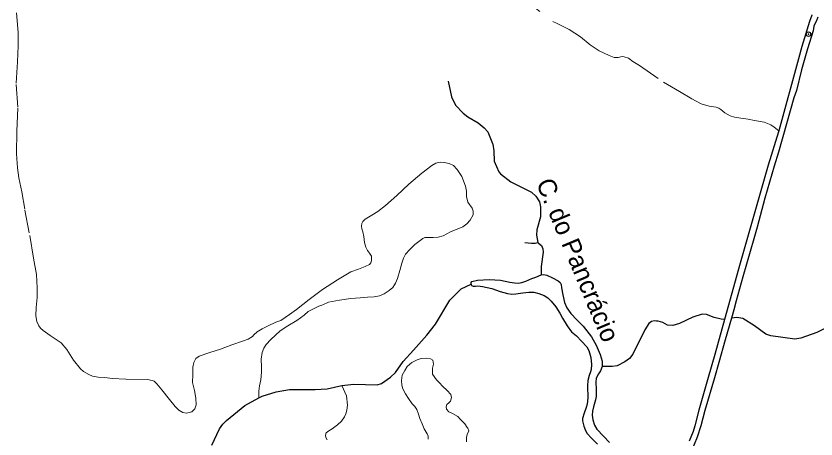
# Model space of a CAD drawing. Extents: x 267.7 to 296, y 7537.7 to 7565.8.
# Drawn here: x 282.492 to 285.983, y 7561.246 to 7563.092 of the extents above; entities that cross this region are included whole.
import ezdxf
from ezdxf.enums import TextEntityAlignment as Align

# ---------------------------------------------------------------- set-up
doc = ezdxf.new("R2010")
doc.units = 0
doc.header["$LTSCALE"] = 0.04
doc.header["$PDMODE"] = 32
doc.header["$PDSIZE"] = 0.02
doc.linetypes.add('SHORT_DASHED', pattern=[2.7, 1.5, -1.2])
for name, color, linetype, lineweight in [('1', 7, 'Continuous', 25), ('2', 7, 'Continuous', 25), ('21', 7, 'SHORT_DASHED', 13), ('7', 7, 'Continuous', 25)]:
    doc.layers.add(name, color=color, linetype=linetype, lineweight=lineweight)
doc.layers.add('61', color=7, linetype='Continuous')

msp = doc.modelspace()

# ---------------------------------------------------------------- linework, layer by layer
at = {"layer": '1'}
for points in [[(285.9657, 7563.0964), (285.9653, 7563.0956), (285.9549, 7563.0678), (285.921, 7562.9592), (285.9071, 7562.9053), (285.8206, 7562.591)], [(285.9911, 7563.087), (285.9863, 7563.0752), (285.985, 7563.072), (285.9745, 7563.0467), (285.9707, 7563.0269), (285.9464, 7562.9487), (285.9206, 7562.8574), (285.898, 7562.7671), (285.8859, 7562.7346), (285.8551, 7562.6218), (285.8204, 7562.4974), (285.8011, 7562.4363), (285.7604, 7562.297), (285.7263, 7562.1699), (285.7119, 7562.1192), (285.6641, 7561.9535), (285.6349, 7561.8489), (285.625, 7561.8093), (285.6145, 7561.7727)], [(285.8206, 7562.591), (285.8193, 7562.5864), (285.7741, 7562.4413), (285.6525, 7562.0129), (285.5847, 7561.7678)], [(285.6145, 7561.7727), (285.587, 7561.6783), (285.5595, 7561.5803), (285.5397, 7561.5137), (285.4984, 7561.37), (285.4808, 7561.3034), (285.4653, 7561.2545), (285.4521, 7561.222), (285.4477, 7561.2121), (285.3927, 7561.0866), (285.3503, 7560.9825), (285.3156, 7560.9005), (285.2639, 7560.7745), (285.2314, 7560.7012), (285.1995, 7560.6192), (285.1598, 7560.5246), (285.1424, 7560.4856)], [(285.5847, 7561.7678), (285.5421, 7561.6149), (285.5126, 7561.515), (285.4726, 7561.3724), (285.4544, 7561.3029), (285.4474, 7561.2795), (285.4292, 7561.236)]]:
    msp.add_lwpolyline(points, dxfattribs=at)
msp.add_point((285.9505, 7563.0123), dxfattribs=at)
at = {"layer": '2'}
for points in [[(284.4779, 7561.9218), (284.4782, 7561.929), (284.4813, 7561.9328), (284.5063, 7561.9389), (284.5571, 7561.9419), (284.6072, 7561.9389), (284.6474, 7561.9306), (284.6671, 7561.9268), (284.6846, 7561.926), (284.6997, 7561.9283), (284.7164, 7561.9351), (284.743, 7561.9465), (284.7612, 7561.9526), (284.7834, 7561.9622)], [(284.7834, 7561.9622), (284.7938, 7561.9639), (284.8082, 7561.9617), (284.834, 7561.9495), (284.8575, 7561.9359), (284.8666, 7561.9283), (284.8712, 7561.9207), (284.8734, 7561.9055), (284.8787, 7561.8752), (284.8856, 7561.841), (284.8954, 7561.8191), (284.9136, 7561.794), (284.9394, 7561.766), (284.9667, 7561.7386), (285.0031, 7561.6916), (285.0236, 7561.6552), (285.0418, 7561.615), (285.0502, 7561.5854), (285.0504, 7561.5627)], [(284.4779, 7561.9218), (284.4805, 7561.9161), (284.4866, 7561.9131), (284.4979, 7561.9131), (284.5078, 7561.9146), (284.5283, 7561.9108), (284.5693, 7561.9025), (284.6049, 7561.8896), (284.6375, 7561.8813), (284.6565, 7561.8782), (284.6732, 7561.8797), (284.7043, 7561.8835), (284.7301, 7561.8873), (284.7513, 7561.8866), (284.7741, 7561.8813), (284.7968, 7561.8721), (284.8135, 7561.8615), (284.8279, 7561.8471), (284.8484, 7561.8221), (284.8658, 7561.7948), (284.8765, 7561.7728), (284.8977, 7561.7402), (284.9167, 7561.7136), (284.9379, 7561.6969), (284.9607, 7561.6726), (284.9834, 7561.6476), (284.9918, 7561.6317), (285.0001, 7561.6013), (285.0031, 7561.5718), (285.0024, 7561.5498), (284.9994, 7561.5391), (284.9933, 7561.5225), (284.9872, 7561.5012), (284.9857, 7561.4785), (284.9872, 7561.4261), (284.9849, 7561.3988), (284.9804, 7561.3829), (284.9713, 7561.3586), (284.9645, 7561.3358), (284.9645, 7561.3252), (284.9698, 7561.3017), (284.9781, 7561.2827), (284.9842, 7561.2706), (285.0039, 7561.2494), (285.0305, 7561.2243)], [(285.0504, 7561.5627), (285.0426, 7561.5437), (285.0342, 7561.5308), (285.0274, 7561.5171), (285.0244, 7561.5096), (285.0229, 7561.4951), (285.0236, 7561.461), (285.0236, 7561.4314), (285.0214, 7561.417), (285.013, 7561.3859), (285.0085, 7561.3677), (285.0069, 7561.3495), (285.0092, 7561.3305), (285.016, 7561.307), (285.0267, 7561.2888), (285.0555, 7561.2592), (285.0828, 7561.2312)]]:
    msp.add_lwpolyline(points, dxfattribs=at)
at = {"layer": '21'}
for points in [[(284.6998, 7563.1725), (284.835, 7563.0678), (284.8541, 7563.0587), (284.9068, 7563.0327), (284.9557, 7563.0006), (284.9985, 7562.9662), (285.0375, 7562.9395), (285.0802, 7562.9196), (285.1031, 7562.9112), (285.1207, 7562.9105), (285.1375, 7562.9143), (285.1459, 7562.9135), (285.1658, 7562.9074), (285.1841, 7562.8937), (285.2124, 7562.8753), (285.3178, 7562.8028), (285.3881, 7562.7623), (285.4408, 7562.7309), (285.482, 7562.708), (285.5164, 7562.6981), (285.547, 7562.6935), (285.56, 7562.6889), (285.5676, 7562.6836), (285.5859, 7562.6698), (285.6081, 7562.6568), (285.6279, 7562.65), (285.6547, 7562.6462), (285.6868, 7562.6416), (285.7143, 7562.6355), (285.7578, 7562.6278), (285.7861, 7562.6164), (285.8006, 7562.6064), (285.8206, 7562.591)], [(283.5052, 7561.6814), (283.485, 7561.6738), (283.4345, 7561.657), (283.3841, 7561.6384), (283.3386, 7561.6233), (283.2915, 7561.6081), (283.2772, 7561.5972), (283.2679, 7561.5804), (283.2637, 7561.5602), (283.2637, 7561.5274), (283.2629, 7561.492), (283.2713, 7561.4575), (283.2772, 7561.4247), (283.2789, 7561.3953), (283.2721, 7561.3776), (283.2595, 7561.365), (283.236, 7561.3591), (283.2208, 7561.3616), (283.2023, 7561.3717), (283.1863, 7561.3885), (283.1619, 7561.4188), (283.1291, 7561.4609), (283.1064, 7561.487), (283.0954, 7561.4979), (283.087, 7561.5021), (283.066, 7561.5055), (282.9717, 7561.5072), (282.9112, 7561.5097), (282.88, 7561.5139), (282.8514, 7561.5164), (282.8253, 7561.5198), (282.8093, 7561.5282), (282.7866, 7561.54), (282.774, 7561.5526), (282.7437, 7561.5905), (282.7134, 7561.6368), (282.689, 7561.6662), (282.6411, 7561.6982), (282.6108, 7561.7201), (282.599, 7561.7302), (282.5922, 7561.7394), (282.583, 7561.7588), (282.5788, 7561.784), (282.5796, 7561.8194), (282.5838, 7561.8631), (282.5838, 7561.906), (282.5813, 7561.9641), (282.5687, 7562.0356), (282.5502, 7562.1458), (282.53, 7562.2493), (282.5174, 7562.3242), (282.5047, 7562.3856), (282.4988, 7562.4286), (282.4946, 7562.4908), (282.4963, 7562.5893), (282.4997, 7562.6936), (282.4921, 7562.798), (282.4988, 7562.8922), (282.5014, 7562.962), (282.5014, 7563.0193), (282.4938, 7563.1059)], [(283.5524, 7561.4254), (283.5515, 7561.4542), (283.5549, 7561.4786), (283.5608, 7561.5038), (283.5633, 7561.5375), (283.5641, 7561.561), (283.5624, 7561.5938), (283.5667, 7561.6233), (283.5742, 7561.6426), (283.5843, 7561.6586), (283.6045, 7561.6797), (283.6247, 7561.6999), (283.6449, 7561.7175), (283.6786, 7561.7403), (283.7181, 7561.7638), (283.7492, 7561.7865), (283.7678, 7561.8025), (283.7871, 7561.8126), (283.8132, 7561.8261), (283.8309, 7561.832), (283.8553, 7561.8438), (283.9032, 7561.8522), (283.9537, 7561.8589), (283.9941, 7561.8614), (284.0261, 7561.8648), (284.0555, 7561.8665), (284.0791, 7561.8707), (284.0993, 7561.8791), (284.1212, 7561.8934), (284.1363, 7561.9077), (284.1481, 7561.9262), (284.1565, 7561.9464), (284.1666, 7561.9818), (284.1759, 7562.0137), (284.1826, 7562.0356), (284.1919, 7562.0524), (284.2104, 7562.0735), (284.2331, 7562.0953), (284.2676, 7562.1214), (284.2768, 7562.1248), (284.2945, 7562.1248), (284.313, 7562.1248), (284.3349, 7562.1273), (284.3568, 7562.1332), (284.3879, 7562.15), (284.4418, 7562.1719), (284.4594, 7562.1845), (284.4737, 7562.2005), (284.4872, 7562.2241), (284.4872, 7562.2409), (284.4822, 7562.2535), (284.4636, 7562.2788), (284.4577, 7562.3049), (284.4577, 7562.3276), (284.4544, 7562.3486), (284.4376, 7562.3915), (284.4174, 7562.4218), (284.4014, 7562.4395), (284.3829, 7562.4479), (284.361, 7562.453), (284.3425, 7562.4538), (284.324, 7562.4496), (284.3063, 7562.4395), (284.2625, 7562.4067), (284.2062, 7562.3579), (284.154, 7562.3091), (284.1052, 7562.2645), (284.0715, 7562.2384), (284.0446, 7562.2224), (284.016, 7562.2056), (284.0059, 7562.1946), (284.0008, 7562.1862), (283.9992, 7562.1744), (284.0017, 7562.1627), (284.0059, 7562.15), (284.0101, 7562.129), (284.0135, 7562.1038), (284.0194, 7562.0836), (284.0261, 7562.0684), (284.0353, 7562.0575), (284.0429, 7562.0432), (284.0438, 7562.0247), (284.0412, 7562.0154), (284.0345, 7562.0078), (284.016, 7561.9994), (283.9865, 7561.9876), (283.9537, 7561.975), (283.8957, 7561.9405), (283.8292, 7561.8984), (283.772, 7561.8555), (283.7164, 7561.8118), (283.6861, 7561.7899), (283.6474, 7561.763), (283.6256, 7561.7554), (283.5927, 7561.7403)], [(283.5927, 7561.7403), (283.5667, 7561.7268), (283.5439, 7561.7133), (283.5305, 7561.7007), (283.5246, 7561.694), (283.5052, 7561.6814)], [(284.1912, 7561.4438), (284.1803, 7561.4656), (284.1761, 7561.4815), (284.1744, 7561.5008), (284.1778, 7561.5252), (284.1895, 7561.5444), (284.1996, 7561.5621), (284.2197, 7561.5797), (284.2432, 7561.5914), (284.2608, 7561.5973), (284.2818, 7561.599), (284.3011, 7561.5964), (284.3111, 7561.5897), (284.3145, 7561.5721), (284.3103, 7561.5553), (284.3103, 7561.5285), (284.3271, 7561.5042), (284.3405, 7561.4916), (284.3539, 7561.4773), (284.374, 7561.4572), (284.3891, 7561.4404), (284.3933, 7561.427), (284.3883, 7561.4111), (284.3807, 7561.4044), (284.3724, 7561.396), (284.369, 7561.3868), (284.3707, 7561.3767), (284.3807, 7561.3649), (284.3967, 7561.3574), (284.421, 7561.3448), (284.4311, 7561.3331), (284.4512, 7561.3129), (284.4613, 7561.297), (284.4646, 7561.2928), (284.468, 7561.2811), (284.4604, 7561.2651), (284.4579, 7561.2534), (284.4579, 7561.2333)], [(283.9354, 7561.3725), (283.9387, 7561.3943), (283.9337, 7561.4346), (283.9146, 7561.4796)], [(284.1912, 7561.4438), (284.2046, 7561.4228), (284.2214, 7561.4002), (284.2331, 7561.3876), (284.2415, 7561.375), (284.2491, 7561.354), (284.2549, 7561.3356), (284.2642, 7561.3121), (284.2734, 7561.2911), (284.2868, 7561.2693), (284.2902, 7561.2584), (284.2902, 7561.2458)], [(283.8724, 7561.2911), (283.8951, 7561.3087), (283.9119, 7561.3238), (283.9253, 7561.3431), (283.932, 7561.3566), (283.9354, 7561.3725)], [(283.8498, 7561.2425), (283.8448, 7561.2526), (283.8431, 7561.2635), (283.8456, 7561.2727), (283.8573, 7561.2819), (283.8724, 7561.2911)]]:
    msp.add_lwpolyline(points, dxfattribs=at)
at = {"layer": '7'}
for points in [[(284.3788, 7562.8072), (284.3929, 7562.7384), (284.4108, 7562.7031), (284.4435, 7562.6671), (284.4637, 7562.6517), (284.5088, 7562.6251), (284.5356, 7562.6031), (284.5505, 7562.5858), (284.5718, 7562.5358), (284.5724, 7562.5327), (284.5781, 7562.5034), (284.579, 7562.4584), (284.5986, 7562.4123), (284.6063, 7562.4027), (284.652, 7562.3679), (284.7412, 7562.3237), (284.76, 7562.3063), (284.7768, 7562.2807), (284.7816, 7562.2592), (284.7809, 7562.2154), (284.7657, 7562.1591), (284.7633, 7562.1352), (284.7698, 7562.1031)], [(284.7124, 7562.104), (284.7425, 7562.1007), (284.7575, 7562.1), (284.7698, 7562.1031)], [(284.7698, 7562.1031), (284.773, 7562.1013), (284.785, 7562.0899), (284.7912, 7562.0765), (284.7926, 7562.0618), (284.7839, 7561.9993), (284.7834, 7561.9622)], [(283.9146, 7561.4796), (283.9667, 7561.4848), (284.0687, 7561.4831), (284.0875, 7561.4882), (284.126, 7561.516), (284.1484, 7561.5369), (284.182, 7561.5847), (284.2272, 7561.6334), (284.2847, 7561.6993), (284.3229, 7561.7478), (284.385, 7561.8513), (284.4355, 7561.9014), (284.4779, 7561.9218)], [(286.5022, 7561.8188), (286.4807, 7561.8189), (286.456, 7561.8251), (286.4294, 7561.8394), (286.3924, 7561.8815), (286.3821, 7561.8897), (286.3679, 7561.8943), (286.3144, 7561.8969), (286.291, 7561.8927), (286.261, 7561.8856), (286.223, 7561.8678), (286.1677, 7561.8351), (286.1035, 7561.7795), (286.0399, 7561.7377), (285.9876, 7561.7108), (285.9168, 7561.6859), (285.8915, 7561.6816), (285.786, 7561.6958), (285.7642, 7561.7039), (285.7143, 7561.7406), (285.6641, 7561.7725), (285.6376, 7561.7756), (285.6145, 7561.7727)], [(285.5847, 7561.7678), (285.5691, 7561.7696), (285.5386, 7561.7765), (285.5048, 7561.7887), (285.486, 7561.7909), (285.4454, 7561.7774), (285.3883, 7561.7504), (285.3586, 7561.7415), (285.3346, 7561.7433), (285.3145, 7561.7548), (285.2945, 7561.76), (285.2878, 7561.7607), (285.2788, 7561.7617), (285.2649, 7561.7583), (285.2545, 7561.7496), (285.2362, 7561.7218), (285.1842, 7561.617), (285.1696, 7561.598), (285.1489, 7561.5822), (285.116, 7561.566), (285.0934, 7561.5618), (285.0504, 7561.5627)], [(283.5524, 7561.4254), (283.5669, 7561.4331), (283.628, 7561.4516), (283.6855, 7561.4618), (283.798, 7561.4623), (283.8495, 7561.4656), (283.9146, 7561.4796)], [(283.3464, 7561.2187), (283.3797, 7561.2905), (283.3952, 7561.3107), (283.4114, 7561.327), (283.4905, 7561.3922), (283.5524, 7561.4254)]]:
    msp.add_lwpolyline(points, dxfattribs=at)

# ---------------------------------------------------------------- texts
at = {"layer": '61'}
msp.add_text('C. do Pancrácio', height=0.08, rotation=292.714, dxfattribs=at).set_placement((284.9075, 7562.0121), align=Align.CENTER)

doc.saveas('drawing.dxf')
